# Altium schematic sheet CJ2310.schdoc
size 127 x 101 mm
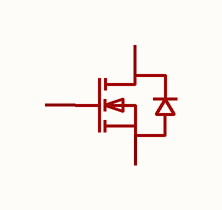
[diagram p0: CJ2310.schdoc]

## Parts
Q?  cj2310  [SOT-23-3_L2.9-W1.6-P1.90-LS2.8-BR]  (value not drawn)

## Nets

Not connected (* = marked no-connect by the designer): Q? 1(G) 2(S) 3(D)

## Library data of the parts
Q? = cj2310: 数量:1个N沟道;漏源电压(Vdss):60V;连续漏极电流(Id):3A;导通电阻(RDS(on)):125mΩ@4.5V;耗散功率(Pd):350mW;阈值电压(Vgs(th)):500mV;; Manufacturer: CJ(江苏长电/长晶); AddInBom: yes; ModelId: 89cb27a44ab2466697082bb9fd73a7d0; ModelName: SOT-23-3L_L2.9-W1.6-H1.1-LS2.8-P0.95; ModelTransform: 114.173,110.236,0,90,0,0,0,0,0; Number: 1个N沟道; Drain to Source Voltage: 60V; Current - Continuous Drain(Id): 3A; Pd - Power Dissipation: 350mW; Gate Threshold Voltage (Vgs(th)): 500mV; Gate Charge(Qg): 6nC@10V; Input Capacitance(Ciss): 247pF; Reverse Transfer Capacitance (Crss@Vds): 19.5pF; Type: N沟道; Output Capacitance(Coss): 34pF; Vgs: ±20V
